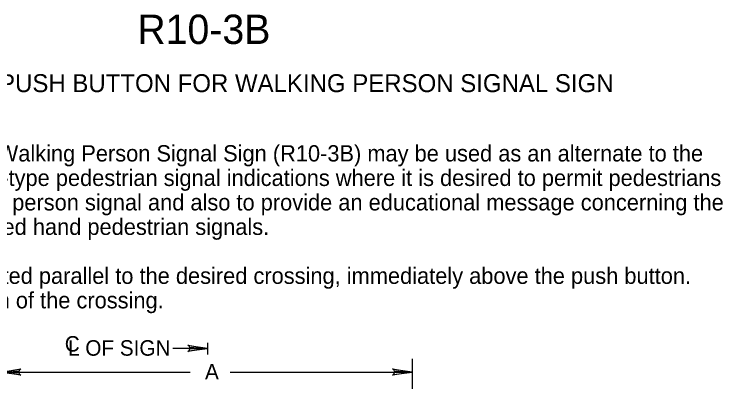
# Model space of a CAD drawing. Extents: x 0.013 to 0.191, y 0.004 to 0.259.
# Drawn here: x 0.0801 to 0.1888, y 0.2028 to 0.2591 of the extents above; entities that cross this region are included whole.
import ezdxf

# ---------------------------------------------------------------- set-up
doc = ezdxf.new("R2010")
doc.units = 0
for name, color, linetype in [('1', 7, 'Continuous'), ('12', 7, 'Continuous'), ('2', 7, 'Continuous'), ('3', 7, 'Continuous')]:
    doc.layers.add(name, color=color, linetype=linetype)

# ---------------------------------------------------------------- blocks, each defined once
blk = doc.blocks.new('RARROW')
at = {"layer": '3'}
for p, q in [((-2.156, 0.28500000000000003), (-2.2665, 0.384625)), ((-2.2665, 0.384625), (0, 0)), ((0, 0), (-2.2665, -0.379125)), ((-2.156, 0.28500000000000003), (-2.075625, 0.12075)), ((0, 0), (-2.156, 0.28500000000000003)), ((-2.14975, -0.2705), (0, 0)), ((-2.075625, 0.12075), (0, 0)), ((0, 0), (-2.074, -0.108)), ((-2.2665, -0.379125), (-2.14975, -0.2705)), ((-2.074, -0.108), (-2.14975, -0.2705))]:
    blk.add_line(p, q, dxfattribs=at)

msp = doc.modelspace()

# ---------------------------------------------------------------- linework, layer by layer
at = {"layer": '1'}
for p, q in [((0.10975, 0.207875), (0.1044362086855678, 0.207875)), ((0.141125, 0.20625000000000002), (0.141125, 0.19425)), ((0.078125, 0.20425000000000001), (0.107125, 0.20425000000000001)), ((0.11325, 0.20425000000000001), (0.141125, 0.20425000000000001))]:
    msp.add_line(p, q, dxfattribs=at)
at = {"layer": '12'}
msp.add_line((0.10978870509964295, 0.20693282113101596), (0.10978870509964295, 0.20872219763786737), dxfattribs=at)

# ---------------------------------------------------------------- block references
at = {"layer": '3', "xscale": 0.0013236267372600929, "yscale": 0.001309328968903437}
for p in [(0.10975, 0.207875), (0.141125, 0.20425000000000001)]:
    msp.add_blockref('RARROW', p, dxfattribs=at)
at = {"layer": '3', "xscale": 0.0013236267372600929, "yscale": 0.001309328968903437, "rotation": 180}
msp.add_blockref('RARROW', (0.078125, 0.20425000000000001), dxfattribs=at)

# ---------------------------------------------------------------- texts
at = {"layer": '1'}
for s, height, p in [('R10-3B', 0.0045000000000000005, (0.099, 0.2545)), ('EDUCATIONAL PUSH BUTTON FOR WALKING PERSON SIGNAL SIGN', 0.00275025, (0.050625, 0.247125))]:
    msp.add_text(s, height=height, dxfattribs=at).set_placement(p)
at = {"layer": '2'}
for s, p in [('   The Educational Push Button for Walking Person Signal Sign (R10-3B) may be used as an alternate to the', (0.025750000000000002, 0.23650025)), ('R10-3 sign at locations with symbol-type pedestrian signal indications where it is desired to permit pedestrians', (0.025750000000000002, 0.2327505)), ('to register a demand for the walking person signal and also to provide an educational message concerning the', (0.025750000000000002, 0.22900075)), ('meaning of walking person /  upraised hand pedestrian signals.', (0.025750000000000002, 0.225251)), ('   The R10-3B sign should be mounted parallel to the desired crossing, immediately above the push button.  ', (0.025750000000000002, 0.2177515)), ('The arrow shall point in the direction of the crossing.', (0.025750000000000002, 0.21400175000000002))]:
    msp.add_text(s, height=0.0024997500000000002, dxfattribs=at).set_placement(p)
at = {"layer": '3'}
for s, p in [('C', (0.08787500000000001, 0.207375)), ('L OF SIGN', (0.088375, 0.20675000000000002)), ('A', (0.109375, 0.203125))]:
    msp.add_text(s, height=0.0023752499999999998, dxfattribs=at).set_placement(p)

doc.saveas('drawing.dxf')
